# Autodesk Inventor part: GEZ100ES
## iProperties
Company: Mountain Blue Industries Ltd.
Category: Bearings
Manager: Cbliss
Shininess: 64.0
Length Units: 11272
Angle Units: 11279
Time Units: 11290
Mass Units: 11286
Length Display Precision: 3
Angle Display Precision: 2
Compacted: True
Part Number: GEZ100ES
Document SubType Name: Modeling
Created: 2003-01
Designer: QBZ
Cost Center: 36.71
Material: Steel, High Strength Low Alloy
Description: 1 x 1-5/8 SA Bearing
Catalog Web Link: http://www.herculeshydraulics.com/
Vendor: Hercules Hydraulics
Density: 0.0
Volumn: 0.0
Area: 0.0
PropertySet Name: Model Information
Control State: 0
Master: False
Checked Out: False
Length: 1
Author: QBZ
Revision Number: A
Title: Self Aligning Spherical Bearing
Subject: Hyd Cylinder End Bearings
Keywords: SA Bearing
Comments: Although generic in nature as supplied through a hydraulic component supplier, the dims should quite accurately match any brand of Bearing i.e NTN, SKF, IKO, FAG, etc.
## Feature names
1. Revolution1
2. Revolution2
3. Hole1
4. Fillet1
